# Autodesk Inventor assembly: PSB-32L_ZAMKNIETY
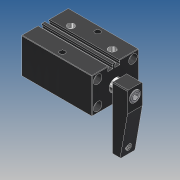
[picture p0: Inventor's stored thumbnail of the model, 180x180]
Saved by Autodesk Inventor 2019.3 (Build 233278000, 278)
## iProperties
Created: 2010-02
Part Number: PSB-32L_ZAMKNIETY
Material: Ogólny
Document SubType Name: Assembly
Designer: CADENGINEERING4
Sending System: PRO/ENGINEER BY PARAMETRIC TECHNOLOGY CORPORATION, 2007170
Preprocessor: PRO/ENGINEER BY PARAMETRIC TECHNOLOGY CORPORATION, 2007170
Title: PSB-32_ASM
Author: Administrator
Revision Number: 1LAST_VERSION
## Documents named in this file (6)
- E:\SERWER_ZAPAS\Pneumatic\PSB PNEUMATIC SWING\PSB-32\PSB-32L_ZAMKNIETY.iam
- E:\SERWER_ZAPAS\Pneumatic\PSB PNEUMATIC SWING\PSB-32\PSB-32BT.ipt
- E:\SERWER_ZAPAS\Pneumatic\PSB PNEUMATIC SWING\PSB-32\PSB-32HSG.ipt
- E:\SERWER_ZAPAS\Pneumatic\PSB PNEUMATIC SWING\PSB-32\PSB-32HG.ipt
- E:\SERWER_ZAPAS\Pneumatic\PSB PNEUMATIC SWING\PSB-32\PSB-32YB.ipt
- E:\SERWER_ZAPAS\Pneumatic\PSB PNEUMATIC SWING\PSB-32\M8X20.ipt
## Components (5 placed, 5 different names)
1. PSB-32BT_0 — Zestawiające:1, Kątowe:1
2. PSB-32HSG_1 — Zestawiające:1, Zestawiające:2, Zestawiające:3, Zestawiające:6
3. PSB-32HG_2 — Zestawiające:6
4. PSB-32YB_3 — Zestawiające:2, Zestawiające:3, Zestawiające:4, Zestawiające:5, Kątowe:1
5. M8X20_4 — Zestawiające:4, Zestawiające:5
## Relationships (7: Mate 6, Angle 1)
- Zestawiające:1 [Mate]: PSB-32BT_0 ↔ PSB-32HSG_1
- Zestawiające:2 [Mate]: PSB-32HSG_1 ↔ PSB-32YB_3
- Zestawiające:3 [Mate]: PSB-32HSG_1 ↔ PSB-32YB_3
- Zestawiające:4 [Mate]: PSB-32YB_3 ↔ M8X20_4
- Zestawiające:5 [Mate]: PSB-32YB_3 ↔ M8X20_4
- Kątowe:1 [Angle]: PSB-32BT_0 ↔ PSB-32YB_3
- Zestawiające:6 [Mate]: PSB-32HSG_1 ↔ PSB-32HG_2
